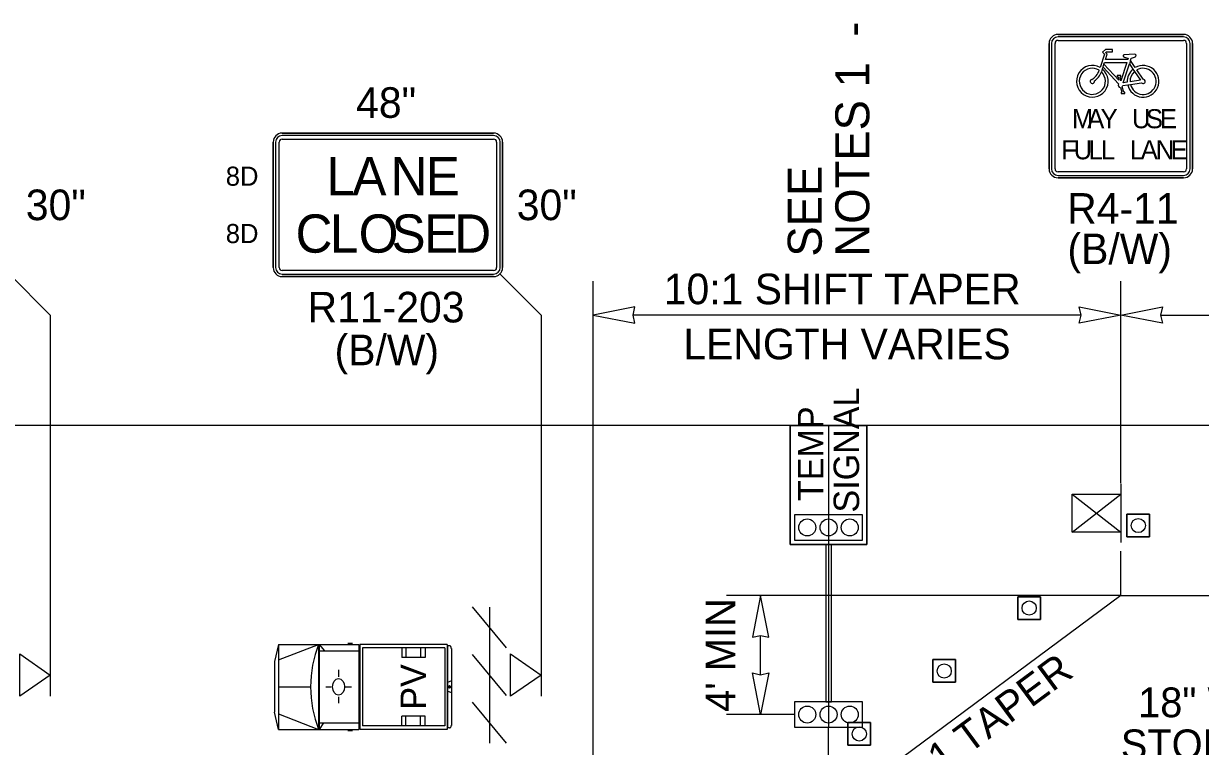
# Model space of a CAD drawing. Extents: x 99979.8 to 100075.7, y 99995 to 100010.7.
# Drawn here: x 100022.228 to 100024.999, y 100007.184 to 100008.886 of the extents above; entities that cross this region are included whole.
import ezdxf

# ---------------------------------------------------------------- set-up
doc = ezdxf.new("R2010")
doc.units = 0
for name, color, linetype in [('RD_ED_ShoulderPavedEdge', 7, 'Continuous'), ('RD_MK_LineEdgeWhite', 7, 'Continuous'), ('TR_SN_ConstructionSigns', 7, 'Continuous'), ('TR_WZ_BarricadeType3', 7, 'Continuous'), ('TR_WZ_PortableSignMount5ftMinBlk-Wht', 7, 'Continuous'), ('TR_WZ_PortableSignMountBlk-Wht', 7, 'Continuous'), ('TR_WZ_ProtectiveVehicle', 7, 'Continuous'), ('TR_WZ_TempSignal', 7, 'Continuous'), ('TR_WZ_TrafficCone', 7, 'Continuous'), ('TR_WZ_WorkZoneDetails', 7, 'Continuous'), ('TR_WZ_WorkZoneTextCurrent', 7, 'Continuous')]:
    doc.layers.add(name, color=color, linetype=linetype)

msp = doc.modelspace()

# ---------------------------------------------------------------- linework, layer by layer
at = {"layer": 'RD_ED_ShoulderPavedEdge'}
msp.add_line((100035.6424, 100007.9393), (100020.3, 100007.9393), dxfattribs=at)
at = {"layer": 'RD_MK_LineEdgeWhite'}
for q in [(100023.5692, 100006.6193), (100035.6425, 100007.5393)]:
    msp.add_line((100024.8112, 100007.5393), q, dxfattribs=at)
at = {"layer": 'TR_SN_ConstructionSigns'}
for p, q in [((100024.6634, 100008.8599), (100024.9588, 100008.8599)), ((100024.9588, 100008.8599), (100024.6634, 100008.8599)), ((100024.9588, 100008.8599), (100024.6634, 100008.8599)), ((100024.9588, 100008.8543), (100024.6634, 100008.8543)), ((100024.6423, 100008.5435), (100024.6423, 100008.8388)), ((100024.6423, 100008.8388), (100024.6423, 100008.5435)), ((100024.6423, 100008.8388), (100024.6423, 100008.5435)), ((100024.648, 100008.8388), (100024.648, 100008.5435)), ((100024.6564, 100008.5435), (100024.6564, 100008.8388)), ((100024.6634, 100008.8458), (100024.9588, 100008.8458)), ((100024.7751, 100008.8247), (100024.7681, 100008.8178)), ((100024.7916, 100008.8247), (100024.7751, 100008.8247)), ((100024.7916, 100008.8192), (100024.7916, 100008.8247)), ((100024.9658, 100008.8388), (100024.9658, 100008.5435)), ((100024.9742, 100008.5435), (100024.9742, 100008.8388)), ((100024.9798, 100008.8388), (100024.9798, 100008.5435)), ((100024.9798, 100008.5435), (100024.9798, 100008.8388)), ((100024.9798, 100008.5435), (100024.9798, 100008.8388)), ((100024.7728, 100008.8131), (100024.7624, 100008.782)), ((100024.7681, 100008.8178), (100024.7728, 100008.8131)), ((100024.775, 100008.8006), (100024.7792, 100008.8131)), ((100024.8276, 100008.8006), (100024.775, 100008.8006)), ((100024.7752, 100008.8171), (100024.7774, 100008.8192)), ((100024.7792, 100008.8131), (100024.7752, 100008.8171)), ((100024.7774, 100008.8192), (100024.7916, 100008.8192)), ((100024.8435, 100008.8135), (100024.8186, 100008.8118)), ((100024.8288, 100008.804), (100024.8276, 100008.8006)), ((100024.8338, 100008.7983), (100024.8312, 100008.7904)), ((100024.8338, 100008.7983), (100024.8357, 100008.8041)), ((100024.845, 100008.7818), (100024.8338, 100008.7983)), ((100024.7676, 100008.7784), (100024.7653, 100008.7717)), ((100024.7676, 100008.7784), (100024.7692, 100008.7831)), ((100024.7692, 100008.7831), (100024.7715, 100008.7902)), ((100024.7692, 100008.7831), (100024.8058, 100008.7433)), ((100024.7715, 100008.7902), (100024.7728, 100008.794)), ((100024.8062, 100008.7526), (100024.7715, 100008.7902)), ((100024.7728, 100008.794), (100024.8254, 100008.794)), ((100024.8254, 100008.794), (100024.811, 100008.7507)), ((100024.8164, 100008.7462), (100024.8312, 100008.7904)), ((100024.8312, 100008.7904), (100024.8396, 100008.778)), ((100024.8396, 100008.778), (100024.8433, 100008.7725)), ((100024.8433, 100008.7725), (100024.8571, 100008.7522)), ((100024.8636, 100008.7544), (100024.8487, 100008.7763)), ((100024.8115, 100008.7633), (100024.8027, 100008.7633)), ((100024.8049, 100008.76), (100024.8062, 100008.7526)), ((100024.811, 100008.7507), (100024.8093, 100008.76)), ((100024.8093, 100008.76), (100024.8115, 100008.76)), ((100024.8115, 100008.76), (100024.8115, 100008.7633)), ((100024.816, 100008.7395), (100024.8273, 100008.7411)), ((100024.8264, 100008.7477), (100024.8164, 100008.7462)), ((100024.8273, 100008.7411), (100024.8338, 100008.7421)), ((100024.8571, 100008.7522), (100024.8329, 100008.7486)), ((100024.8338, 100008.7421), (100024.8601, 100008.746)), ((100024.8101, 100008.7352), (100024.8137, 100008.7244)), ((100024.8137, 100008.7244), (100024.8119, 100008.7244)), ((100024.8119, 100008.7244), (100024.8119, 100008.7211)), ((100024.8119, 100008.7211), (100024.8207, 100008.7211)), ((100024.8183, 100008.7244), (100024.8143, 100008.7366)), ((100024.8207, 100008.7244), (100024.8183, 100008.7244)), ((100024.8207, 100008.7211), (100024.8207, 100008.7244)), ((100022.8159, 100008.3112), (100022.8159, 100008.6065)), ((100022.8159, 100008.6065), (100022.8159, 100008.3112)), ((100022.8159, 100008.6065), (100022.8159, 100008.3112)), ((100022.8215, 100008.6065), (100022.8215, 100008.3112)), ((100022.8299, 100008.3112), (100022.8299, 100008.6065)), ((100022.8369, 100008.6276), (100023.3348, 100008.6276)), ((100023.3348, 100008.6276), (100022.8369, 100008.6276)), ((100023.3348, 100008.6276), (100022.8369, 100008.6276)), ((100023.3348, 100008.622), (100022.8369, 100008.622)), ((100022.8369, 100008.6135), (100023.3348, 100008.6135)), ((100023.3418, 100008.6065), (100023.3418, 100008.3112)), ((100023.3502, 100008.3112), (100023.3502, 100008.6065)), ((100023.3559, 100008.6065), (100023.3559, 100008.3112)), ((100023.3559, 100008.3112), (100023.3559, 100008.6065)), ((100023.3559, 100008.3112), (100023.3559, 100008.6065)), ((100024.9588, 100008.5364), (100024.6634, 100008.5364)), ((100024.6634, 100008.528), (100024.9588, 100008.528)), ((100024.9588, 100008.5224), (100024.6634, 100008.5224)), ((100024.6634, 100008.5224), (100024.9588, 100008.5224)), ((100024.6634, 100008.5224), (100024.9588, 100008.5224)), ((100023.3348, 100008.3042), (100022.8369, 100008.3042)), ((100022.8369, 100008.2957), (100023.3348, 100008.2957)), ((100023.3348, 100008.2901), (100022.8369, 100008.2901)), ((100022.8369, 100008.2901), (100023.3348, 100008.2901)), ((100022.8369, 100008.2901), (100023.3348, 100008.2901))]:
    msp.add_line(p, q, dxfattribs=at)
msp.add_lwpolyline([(100024.8027, 100008.7633), (100024.8027, 100008.76), (100024.8049, 100008.76)], dxfattribs=at)
for centre, radius, start, end in [((100024.6634, 100008.8388), 0.0211, 90, 180), ((100024.6634, 100008.8388), 0.0211, 90, 180), ((100024.6634, 100008.8388), 0.0211, 90, 180), ((100024.6634, 100008.8388), 0.0155, 90, 180), ((100024.9588, 100008.8388), 0.0211, 0, 90), ((100024.9588, 100008.8388), 0.0211, 0, 90), ((100024.9588, 100008.8388), 0.0211, 0, 90), ((100024.9588, 100008.8388), 0.0155, 0, 90), ((100024.6634, 100008.8388), 0.00703, 90, 180), ((100024.9588, 100008.8388), 0.00703, 0, 90), ((100024.8186, 100008.8096), 0.00219, 89.3854, 243.6828), ((100024.8438, 100008.8102), 0.00329, 294.5519, 96.4128), ((100024.7441, 100008.7495), 0.0373, 60.5529, 50.868), ((100024.7441, 100008.7495), 0.0307, 58.1532, 46.1649), ((100024.8636, 100008.7495), 0.0373, 130.0889, 182.8379), ((100024.8636, 100008.7495), 0.0373, 192.9622, 119.9648), ((100024.8636, 100008.7495), 0.0307, 131.3616, 181.6359), ((100024.8636, 100008.7495), 0.0307, 193.937, 119.0598), ((100024.7441, 100008.7495), 0.00493, 105.257, 14.3233), ((100024.8106, 100008.7407), 0.00548, 151.1744, 264.8566), ((100024.8636, 100008.7495), 0.00493, 225.1095, 90.4672), ((100024.8106, 100008.7407), 0.00548, 312.0053, 347.2932), ((100022.8369, 100008.6065), 0.0211, 90, 180), ((100022.8369, 100008.6065), 0.0211, 90, 180), ((100022.8369, 100008.6065), 0.0211, 90, 180), ((100022.8369, 100008.6065), 0.0155, 90, 180), ((100022.8369, 100008.6065), 0.00703, 90, 180), ((100023.3348, 100008.6065), 0.0211, 0, 90), ((100023.3348, 100008.6065), 0.0211, 0, 90), ((100023.3348, 100008.6065), 0.0211, 0, 90), ((100023.3348, 100008.6065), 0.0155, 0, 90), ((100023.3348, 100008.6065), 0.00703, 0, 90), ((100024.6634, 100008.5435), 0.0211, 180, 270), ((100024.6634, 100008.5435), 0.0211, 180, 270), ((100024.6634, 100008.5435), 0.0211, 180, 270), ((100024.6634, 100008.5435), 0.0155, 180, 270), ((100024.6634, 100008.5435), 0.00703, 180, 270), ((100024.9588, 100008.5435), 0.0211, 270, 0), ((100024.9588, 100008.5435), 0.0211, 270, 0), ((100024.9588, 100008.5435), 0.0155, 270, 0), ((100024.9588, 100008.5435), 0.00703, 270, 0), ((100024.9588, 100008.5435), 0.0211, 270, 0), ((100022.8369, 100008.3112), 0.0211, 180, 270), ((100022.8369, 100008.3112), 0.0211, 180, 270), ((100022.8369, 100008.3112), 0.0211, 180, 270), ((100022.8369, 100008.3112), 0.0155, 180, 270), ((100022.8369, 100008.3112), 0.00703, 180, 270), ((100023.3348, 100008.3112), 0.0155, 270, 0), ((100023.3348, 100008.3112), 0.00703, 270, 0), ((100023.3348, 100008.3112), 0.0211, 270, 0), ((100023.3348, 100008.3112), 0.0211, 270, 0), ((100023.3348, 100008.3112), 0.0211, 270, 0)]:
    msp.add_arc(centre, radius, start, end, dxfattribs=at)
for centre, major_axis, ratio, start_param, end_param in [((100024.8317, 100008.8148), (-0.0186, 0), 0.588235, 0.686048, 1.410588), ((100024.8317, 100008.8148), (-0.0186, 0), 0.588235, 1.786993, 2.401245), ((100024.749, 100008.7702), (-0.0105, -0.0158), 0.413554, 0.494612, 2.170849), ((100024.749, 100008.7702), (-0.014, -0.021), 0.55814, 0.868091, 1.989998)]:
    msp.add_ellipse(centre, major_axis=major_axis, ratio=ratio, start_param=start_param, end_param=end_param, dxfattribs=at)
at = {"layer": 'TR_WZ_BarricadeType3'}
for p, q in [((100023.3648, 100007.4161), (100023.2848, 100007.5126)), ((100023.3248, 100007.5122), (100023.3248, 100007.1922)), ((100023.3648, 100007.3039), (100023.2848, 100007.4004)), ((100023.3648, 100007.1917), (100023.2848, 100007.2882))]:
    msp.add_line(p, q, dxfattribs=at)
at = {"layer": 'TR_WZ_PortableSignMount5ftMinBlk-Wht'}
for p, q in [((100024.8112, 100007.8019), (100024.8112, 100007.664)), ((100024.6962, 100007.6881), (100024.8112, 100007.7778)), ((100024.6962, 100007.7778), (100024.8112, 100007.6881)), ((100024.7535, 100007.7328), (100024.7535, 100007.7328)), ((100024.7537, 100007.7329), (100024.7537, 100007.7329))]:
    msp.add_line(p, q, dxfattribs=at)
msp.add_lwpolyline([(100024.6962, 100007.6881), (100024.6962, 100007.7778), (100024.8112, 100007.7778), (100024.8112, 100007.6881)], close=True, dxfattribs=at)
at = {"layer": 'TR_WZ_PortableSignMountBlk-Wht'}
for p, q in [((100022.291, 100007.4022), (100022.291, 100007.3022)), ((100023.4466, 100007.4022), (100023.4466, 100007.3022))]:
    msp.add_line(p, q, dxfattribs=at)
for points in [[(100022.291, 100007.3522), (100022.2192, 100007.3022), (100022.2192, 100007.4022)], [(100023.4466, 100007.3522), (100023.3748, 100007.3022), (100023.3748, 100007.4022)]]:
    msp.add_lwpolyline(points, close=True, dxfattribs=at)
at = {"layer": 'TR_WZ_ProtectiveVehicle'}
for p, q in [((100022.8282, 100007.4244), (100022.8189, 100007.3841)), ((100022.8282, 100007.4244), (100022.8282, 100007.2244)), ((100022.8282, 100007.4244), (100023.0171, 100007.4244)), ((100022.8282, 100007.3878), (100022.9226, 100007.4244)), ((100022.9226, 100007.4244), (100022.9226, 100007.2244)), ((100022.9244, 100007.4244), (100022.9244, 100007.2244)), ((100022.9244, 100007.4244), (100022.9364, 100007.4089)), ((100022.9913, 100007.4272), (100023.0027, 100007.4272)), ((100023.0171, 100007.4244), (100023.0171, 100007.2244)), ((100023.2256, 100007.4244), (100023.0198, 100007.4244)), ((100023.0198, 100007.4244), (100023.0198, 100007.2244)), ((100023.2197, 100007.4164), (100023.0257, 100007.4164)), ((100023.0257, 100007.4164), (100023.0257, 100007.2324)), ((100023.1184, 100007.4164), (100023.1184, 100007.3934)), ((100023.1284, 100007.4164), (100023.1284, 100007.3934)), ((100023.1624, 100007.4164), (100023.1624, 100007.3934)), ((100023.1734, 100007.4164), (100023.1734, 100007.3934)), ((100023.2197, 100007.4164), (100023.2197, 100007.2324)), ((100023.2256, 100007.4244), (100023.2256, 100007.2244)), ((100023.2307, 100007.4211), (100023.2263, 100007.4211)), ((100023.2263, 100007.4211), (100023.2263, 100007.2277)), ((100023.2352, 100007.415), (100023.2352, 100007.2338)), ((100022.8189, 100007.3841), (100022.8189, 100007.2648)), ((100022.9244, 100007.4089), (100023.0171, 100007.4089)), ((100023.1734, 100007.3934), (100023.1184, 100007.3934)), ((100022.9697, 100007.3641), (100022.9697, 100007.3479)), ((100023.2352, 100007.3385), (100023.2263, 100007.3348)), ((100022.8282, 100007.3244), (100022.9041, 100007.3244)), ((100022.9395, 100007.3246), (100022.9521, 100007.3245)), ((100022.9704, 100007.286), (100022.9701, 100007.301)), ((100022.9838, 100007.3241), (100022.9838, 100007.3241)), ((100023.0005, 100007.3237), (100022.9857, 100007.324)), ((100023.2352, 100007.3103), (100023.2263, 100007.3141)), ((100023.2328, 100007.3244), (100023.2287, 100007.3244)), ((100023.2307, 100007.3272), (100023.2307, 100007.3216)), ((100022.8282, 100007.2244), (100022.8189, 100007.2648)), ((100022.8282, 100007.261), (100022.9226, 100007.2244)), ((100023.1184, 100007.2324), (100023.1184, 100007.2554)), ((100023.1734, 100007.2554), (100023.1184, 100007.2554)), ((100023.1284, 100007.2324), (100023.1284, 100007.2554)), ((100023.1624, 100007.2324), (100023.1624, 100007.2554)), ((100023.1734, 100007.2324), (100023.1734, 100007.2554)), ((100022.8282, 100007.2244), (100023.0171, 100007.2244)), ((100022.9244, 100007.2399), (100023.0171, 100007.2399)), ((100022.9343, 100007.2399), (100022.9244, 100007.2244)), ((100022.9913, 100007.2216), (100023.0027, 100007.2216)), ((100023.2256, 100007.2244), (100023.0198, 100007.2244)), ((100023.2197, 100007.2324), (100023.0257, 100007.2324)), ((100023.2307, 100007.2277), (100023.2263, 100007.2277))]:
    msp.add_line(p, q, dxfattribs=at)
for centre, major_axis, start_param, end_param in [((100023.0576, 100007.3244), (0, -0.2099), 4.215667, 5.208926), ((100023.2307, 100007.415), (0, 0.0061), 4.712389, 6.283185), ((100023.2307, 100007.2338), (0, -0.0061), 0, 1.570796)]:
    msp.add_ellipse(centre, major_axis=major_axis, ratio=0.73155, start_param=start_param, end_param=end_param, dxfattribs=at)
for centre, major_axis in [((100022.9697, 100007.3244), (0, 0.0193)), ((100023.2307, 100007.3244), (0, 0.00282))]:
    msp.add_ellipse(centre, major_axis=major_axis, ratio=0.73155, dxfattribs=at)
at = {"layer": 'TR_WZ_TempSignal'}
for p, q in [((100024.033, 100007.6596), (100024.033, 100007.9397)), ((100024.033, 100007.9397), (100024.2131, 100007.9397)), ((100024.2131, 100007.9397), (100024.033, 100007.9397)), ((100024.033, 100007.9397), (100024.033, 100007.6596)), ((100024.1231, 100007.9397), (100024.1231, 100007.2294)), ((100024.2131, 100007.9397), (100024.2131, 100007.6596)), ((100024.2131, 100007.6596), (100024.2131, 100007.9397)), ((100024.203, 100007.7295), (100024.0432, 100007.7295)), ((100024.0432, 100007.7295), (100024.0432, 100007.6696)), ((100024.203, 100007.6696), (100024.203, 100007.7295)), ((100024.0432, 100007.6696), (100024.203, 100007.6696)), ((100024.2131, 100007.6596), (100024.033, 100007.6596)), ((100024.033, 100007.6596), (100024.1164, 100007.6596)), ((100024.1298, 100007.6596), (100024.1164, 100007.6596)), ((100024.1164, 100007.6596), (100024.1164, 100007.2893)), ((100024.1164, 100007.6596), (100024.1298, 100007.6596)), ((100024.1298, 100007.2893), (100024.1298, 100007.6596)), ((100024.1298, 100007.6596), (100024.2131, 100007.6596)), ((100024.203, 100007.2893), (100024.0432, 100007.2893)), ((100024.0432, 100007.2893), (100024.0432, 100007.2294)), ((100024.1164, 100007.2893), (100024.1298, 100007.2893)), ((100024.203, 100007.2294), (100024.203, 100007.2893)), ((100024.0432, 100007.2294), (100024.203, 100007.2294))]:
    msp.add_line(p, q, dxfattribs=at)
for points in [[(100024.0432, 100007.7295), (100024.0432, 100007.6696), (100024.203, 100007.6696), (100024.203, 100007.7295), (100024.0432, 100007.7295)], [(100024.0432, 100007.2893), (100024.0432, 100007.2294), (100024.203, 100007.2294), (100024.203, 100007.2893), (100024.0432, 100007.2893)]]:
    msp.add_lwpolyline(points, dxfattribs=at)
for centre in [(100024.0731, 100007.6995), (100024.0731, 100007.6995), (100024.1231, 100007.6995), (100024.1231, 100007.6995), (100024.173, 100007.6995), (100024.173, 100007.6995), (100024.0731, 100007.2593), (100024.0731, 100007.2593), (100024.1231, 100007.2593), (100024.1231, 100007.2593), (100024.173, 100007.2593), (100024.173, 100007.2593)]:
    msp.add_circle(centre, 0.02, dxfattribs=at)
at = {"layer": 'TR_WZ_TrafficCone'}
for points in [[(100024.8789, 100007.6773), (100024.8256, 100007.6773), (100024.8256, 100007.7306), (100024.8789, 100007.7306), (100024.8789, 100007.6773)], [(100024.8789, 100007.7306), (100024.8256, 100007.7306), (100024.8256, 100007.6773), (100024.8789, 100007.6773), (100024.8789, 100007.7306)], [(100024.6221, 100007.4832), (100024.5687, 100007.4832), (100024.5687, 100007.5366), (100024.6221, 100007.5366), (100024.6221, 100007.4832)], [(100024.6221, 100007.5366), (100024.5687, 100007.5366), (100024.5687, 100007.4832), (100024.6221, 100007.4832), (100024.6221, 100007.5366)], [(100024.4221, 100007.3351), (100024.3687, 100007.3351), (100024.3687, 100007.3884), (100024.4221, 100007.3884), (100024.4221, 100007.3351)], [(100024.4221, 100007.3884), (100024.3687, 100007.3884), (100024.3687, 100007.3351), (100024.4221, 100007.3351), (100024.4221, 100007.3884)], [(100024.2221, 100007.1869), (100024.1687, 100007.1869), (100024.1687, 100007.2403), (100024.2221, 100007.2403), (100024.2221, 100007.1869)], [(100024.2221, 100007.2403), (100024.1687, 100007.2403), (100024.1687, 100007.1869), (100024.2221, 100007.1869), (100024.2221, 100007.2403)]]:
    msp.add_lwpolyline(points, dxfattribs=at)
for centre in [(100024.8523, 100007.704), (100024.5954, 100007.5099), (100024.3954, 100007.3617), (100024.1954, 100007.2136)]:
    msp.add_circle(centre, 0.0167, dxfattribs=at)
at = {"layer": 'TR_WZ_WorkZoneDetails'}
for p, q in [((100022.1941, 100008.2963), (100022.291, 100008.1993)), ((100023.3497, 100008.2963), (100023.4466, 100008.1993)), ((100023.5692, 100006.2193), (100023.5692, 100008.2793)), ((100024.8112, 100007.804), (100024.8112, 100008.2793)), ((100022.291, 100008.1993), (100022.291, 100007.4022)), ((100023.4466, 100008.1993), (100023.4466, 100007.4022)), ((100024.7175, 100008.1993), (100023.6629, 100008.1993)), ((100024.9049, 100008.1993), (100025.4071, 100008.1993)), ((100024.8112, 100007.5393), (100024.8112, 100007.644)), ((100024.0432, 100007.5393), (100023.8832, 100007.5393)), ((100024.8112, 100007.5393), (100024.0432, 100007.5393)), ((100023.9632, 100007.353), (100023.9632, 100007.4456)), ((100024.0432, 100007.2593), (100023.8832, 100007.2593)), ((100024.1231, 100004.9817), (100024.1231, 100007.2294))]:
    msp.add_line(p, q, dxfattribs=at)
for points in [[(100023.5692, 100008.1993), (100023.6675, 100008.18), (100023.6629, 100008.1993), (100023.6675, 100008.2186)], [(100024.8112, 100008.1993), (100024.7129, 100008.18), (100024.7175, 100008.1993), (100024.7129, 100008.2186)], [(100024.8112, 100008.1993), (100024.9095, 100008.2186), (100024.9049, 100008.1993), (100024.9095, 100008.18)], [(100023.9632, 100007.5393), (100023.9439, 100007.441), (100023.9632, 100007.4456), (100023.9825, 100007.441)], [(100023.9632, 100007.2593), (100023.9439, 100007.3576), (100023.9632, 100007.353), (100023.9825, 100007.3576)]]:
    msp.add_lwpolyline(points, close=True, dxfattribs=at)

# ---------------------------------------------------------------- texts
at = {"layer": 'TR_SN_ConstructionSigns'}
for s, p in [('48"', (100023.0111, 100008.6636)), ('30"', (100022.2335, 100008.4228)), ('30"', (100023.3891, 100008.4228)), ('R4-11', (100024.6848, 100008.4144)), ('(B/W)', (100024.6856, 100008.3193)), ('R11-203', (100022.8969, 100008.1821)), ('(B/W)', (100022.9603, 100008.0813))]:
    msp.add_text(s, height=0.072, rotation=360, dxfattribs=at).set_placement(p)
for s, height, p in [('M', 0.045, (100024.6961, 100008.6391)), ('A', 0.045, (100024.7321, 100008.6391)), ('Y', 0.045, (100024.7636, 100008.6391)), ('U', 0.045, (100024.8374, 100008.6391)), ('S', 0.045, (100024.8703, 100008.6391)), ('E', 0.045, (100024.9031, 100008.6391)), ('F', 0.045, (100024.6709, 100008.566)), ('U', 0.045, (100024.7002, 100008.566)), ('L', 0.045, (100024.7353, 100008.566)), ('L', 0.045, (100024.7645, 100008.566)), ('L', 0.045, (100024.8325, 100008.566)), ('A', 0.045, (100024.8581, 100008.566)), ('N', 0.045, (100024.8932, 100008.566)), ('E', 0.045, (100024.9283, 100008.566)), ('8D', 0.045, (100022.7043, 100008.5038)), ('L', 0.09, (100022.941, 100008.4813)), ('A', 0.09, (100023.0022, 100008.4813)), ('N', 0.09, (100023.0922, 100008.4813)), ('E', 0.09, (100023.175, 100008.4813)), ('C', 0.09, (100022.8685, 100008.3463)), ('L', 0.09, (100022.9495, 100008.3463)), ('O', 0.09, (100023.017, 100008.3463)), ('S', 0.09, (100023.0944, 100008.3463)), ('E', 0.09, (100023.1709, 100008.3463)), ('D', 0.09, (100023.242, 100008.3463)), ('8D', 0.045, (100022.7043, 100008.3688))]:
    msp.add_text(s, height=height, dxfattribs=at).set_placement(p)
at = {"layer": 'TR_WZ_ProtectiveVehicle'}
msp.add_text('PV', height=0.06, rotation=90, dxfattribs=at).set_placement((100023.1759, 100007.2707))
at = {"layer": 'TR_WZ_TempSignal'}
for s, p in [('SIGNAL', (100024.1951, 100007.7346)), ('TEMP', (100024.1111, 100007.7617))]:
    msp.add_text(s, height=0.06, rotation=90, dxfattribs=at).set_placement(p)
at = {"layer": 'TR_WZ_WorkZoneTextCurrent'}
for s, height, rotation, p in [('-', 0.08, 90, (100024.2191, 100008.8547)), ('NOTES 1', 0.08, 90, (100024.2191, 100008.3369)), ('SEE', 0.08, 90, (100024.1071, 100008.3369)), ("4' MIN", 0.07, 90, (100023.9039, 100007.2654)), ('10:1 TAPER', 0.07, 36.5289, (100024.2858, 100007.0415))]:
    msp.add_text(s, height=height, rotation=rotation, dxfattribs=at).set_placement(p)
for s, height, p in [('10:1 SHIFT TAPER', 0.072, (100023.7352, 100008.2249)), ('LENGTH VARIES', 0.072, (100023.7813, 100008.0953)), ('18" WHITE', 0.07, (100024.8518, 100007.2529)), ('STOP BAR', 0.07, (100024.8112, 100007.1541))]:
    msp.add_text(s, height=height, dxfattribs=at).set_placement(p)

doc.saveas('drawing.dxf')
